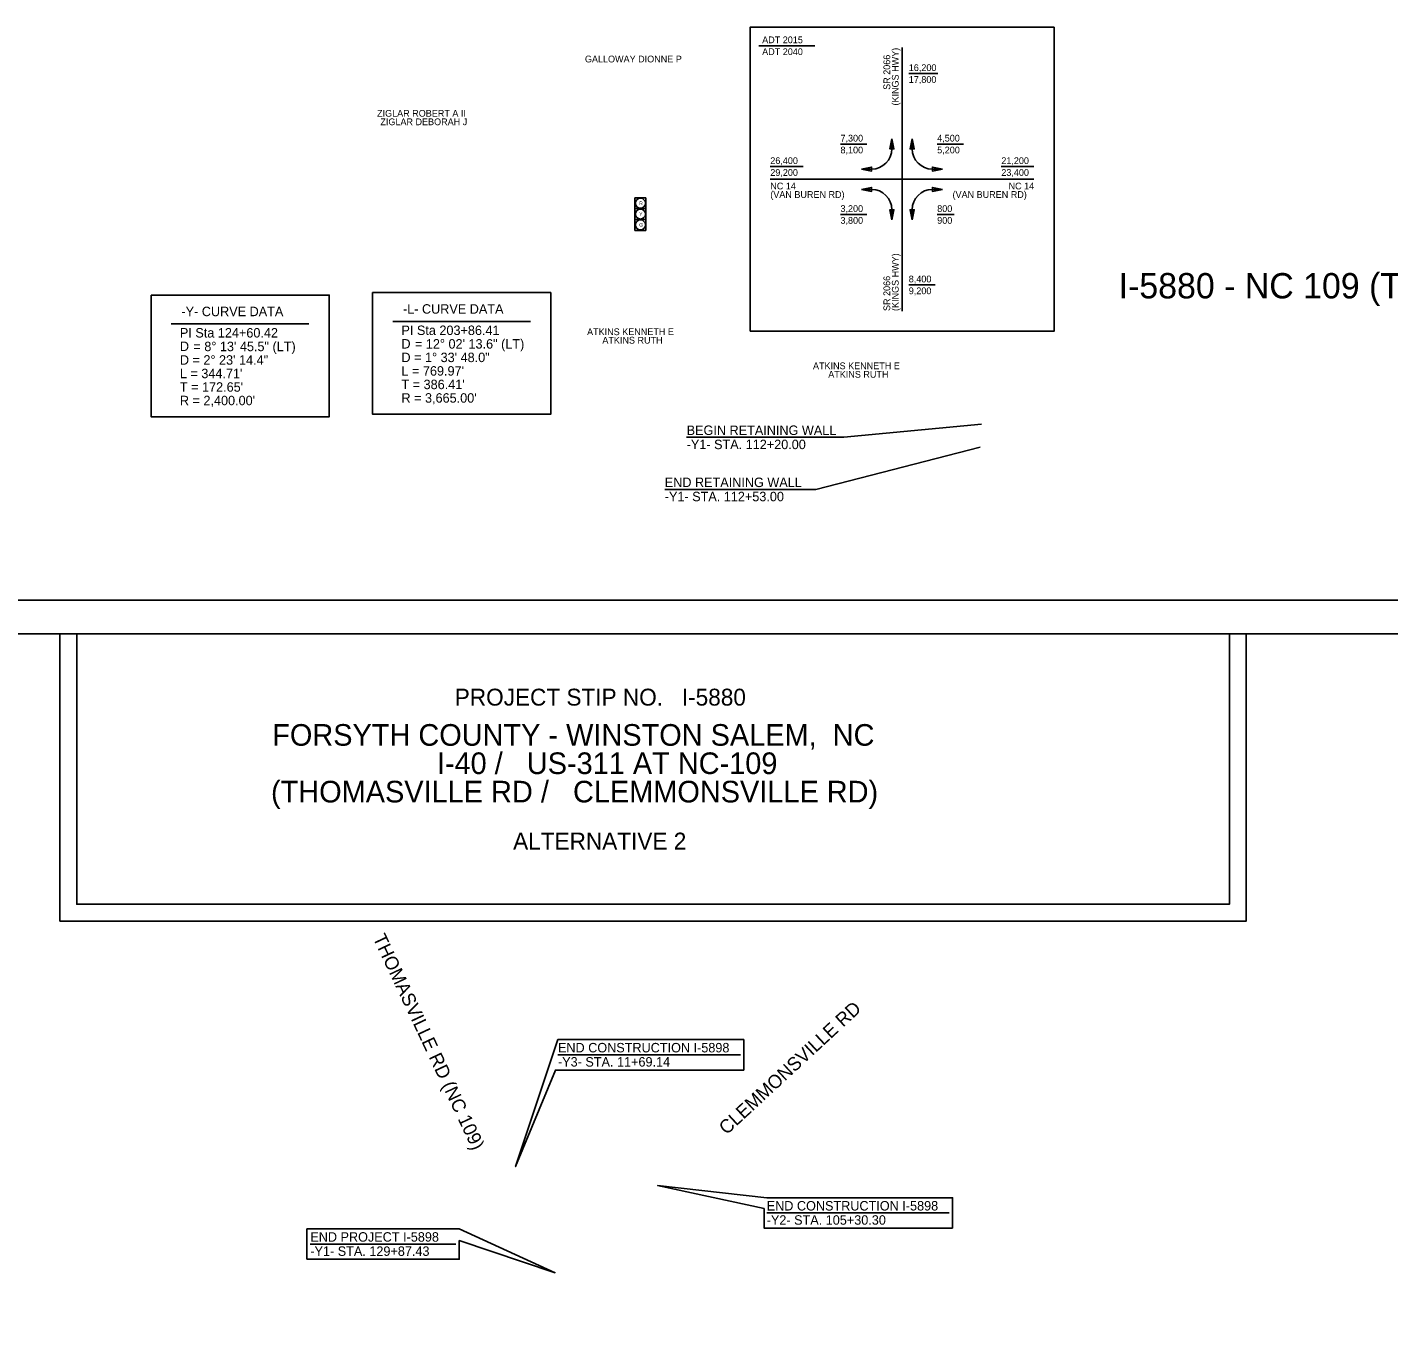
# Model space of a CAD drawing. Extents: x 1636954 to 1644154, y 841334 to 845582.
# Drawn here: x 1639588 to 1641603, y 843634 to 845582 of the extents above; entities that cross this region are included whole.
import ezdxf

# ---------------------------------------------------------------- set-up
doc = ezdxf.new("R2010")
doc.units = 0
for name, color, linetype in [('Default', 7, 'Continuous'), ('Exist Property Line PSD Text', 7, 'Continuous'), ('Exist Roads EOT Text', 7, 'Continuous'), ('Prop CMT Concrete Wall', 7, 'Continuous'), ('Prop Conc 2ft 6in Curb and Gutter', 7, 'Continuous'), ('Prop Horizontal Alignment Curve and Spiral Data', 7, 'Continuous'), ('Prop PHM Label Text', 7, 'Continuous'), ('Prop PHM Legend CELL', 7, 'Continuous'), ('Scratch_Level_0', 7, 'Continuous'), ('Scratch_Level_1', 7, 'Continuous'), ('Sheet Plan And Profile CELL', 7, 'Continuous'), ('Sheet Title CELL', 7, 'Continuous')]:
    doc.layers.add(name, color=color, linetype=linetype)

msp = doc.modelspace()

# ---------------------------------------------------------------- linework, layer by layer
at = {"layer": 'Prop CMT Concrete Wall'}
for points in [[(1640487.3, 845329.3), (1640487.3, 845313.3), (1640503.3, 845313.3), (1640503.3, 845329.3)], [(1640487.3, 845313.3), (1640487.3, 845297.2), (1640503.3, 845297.2), (1640503.3, 845313.3)], [(1640487.3, 845297.2), (1640487.3, 845281.2), (1640503.3, 845281.2), (1640503.3, 845297.2)]]:
    msp.add_lwpolyline(points, close=True, dxfattribs=at)
for centre in [(1640495.4, 845321.3), (1640495.4, 845305.3), (1640495.4, 845289.3)]:
    msp.add_circle(centre, 7.37, dxfattribs=at)
at = {"layer": 'Prop Conc 2ft 6in Curb and Gutter'}
for p, q in [((1641000.5, 844994.5), (1640796.5, 844974.9)), ((1640796.5, 844974.9), (1640563.8, 844974.9)), ((1640998.4, 844960.2), (1640754.8, 844897.8)), ((1640754.8, 844897.8), (1640531.4, 844897.8)), ((1640373.3, 844061.2), (1640643.4, 844061.2)), ((1640682.3, 843827.2), (1640952.4, 843827.2)), ((1640006.7, 843781.1), (1640222.2, 843781.1))]:
    msp.add_line(p, q, dxfattribs=at)
for points in [[(1640648.4, 844038.6), (1640648.4, 844083.7), (1640373.3, 844083.7), (1640310.6, 843895.7), (1640369.5, 844038.6), (1640369.5, 844038.6)], [(1640957.4, 843804.6), (1640957.4, 843849.7), (1640682.3, 843849.7), (1640520.7, 843867.5), (1640678.5, 843833.5), (1640678.5, 843804.6)], [(1640001.7, 843758.5), (1640001.7, 843803.6), (1640227.2, 843803.6), (1640369, 843738.6), (1640227.2, 843786.1), (1640227.2, 843758.5)]]:
    msp.add_lwpolyline(points, close=True, dxfattribs=at)
at = {"layer": 'Prop Horizontal Alignment Curve and Spiral Data'}
for points in [[(1639770.9, 845185.4), (1639770.9, 845005.4), (1640034.6, 845005.4), (1640034.6, 845185.4)], [(1640098.9, 845189.1), (1640098.9, 845009.1), (1640362.6, 845009.1), (1640362.6, 845189.1)]]:
    msp.add_lwpolyline(points, close=True, dxfattribs=at)
at = {"layer": 'Prop PHM Legend CELL'}
for p, q in [((1640670.6, 845554.3), (1640753.6, 845554.3)), ((1640882.6, 845551.8), (1640882.6, 845161.8)), ((1640892.6, 845513.1), (1640935.4, 845513.1)), ((1640791.5, 845408.8), (1640830.5, 845408.8)), ((1640867.6, 845401.8), (1640867.6, 845416.8)), ((1640897.6, 845401.8), (1640897.6, 845416.8)), ((1640934.7, 845408.8), (1640973.7, 845408.8)), ((1640687.6, 845375.5), (1640736.1, 845375.5)), ((1640837.6, 845371.8), (1640822.6, 845371.8)), ((1640927.6, 845371.8), (1640942.6, 845371.8)), ((1641029.6, 845375.5), (1641077.6, 845375.5)), ((1640687.6, 845356.8), (1641077.6, 845356.8)), ((1640837.6, 845341.8), (1640822.6, 845341.8)), ((1640927.6, 845341.8), (1640942.6, 845341.8)), ((1640830.5, 845304.7), (1640791.5, 845304.7)), ((1640867.6, 845311.8), (1640867.6, 845296.8)), ((1640897.6, 845311.8), (1640897.6, 845296.8)), ((1640959.9, 845304.7), (1640934.7, 845304.7)), ((1640931.6, 845200.4), (1640892.6, 845200.4))]:
    msp.add_line(p, q, dxfattribs=at)
for points in [[(1640657.6, 845131.8), (1640657.6, 845581.8), (1641107.6, 845581.8), (1641107.6, 845131.8)], [(1640867.6, 845416.8), (1640870.6, 845401.8), (1640864.6, 845401.8)], [(1640897.6, 845416.8), (1640894.6, 845401.8), (1640900.6, 845401.8)], [(1640822.6, 845371.8), (1640837.6, 845374.8), (1640837.6, 845368.8)], [(1640942.6, 845371.8), (1640927.6, 845374.8), (1640927.6, 845368.8)], [(1640822.6, 845341.8), (1640837.6, 845338.8), (1640837.6, 845344.8)], [(1640942.6, 845341.8), (1640927.6, 845338.8), (1640927.6, 845344.8)], [(1640867.6, 845296.8), (1640870.6, 845311.8), (1640864.6, 845311.8)], [(1640897.6, 845296.8), (1640894.6, 845311.8), (1640900.6, 845311.8)]]:
    msp.add_lwpolyline(points, close=True, dxfattribs=at)
for centre, start, end in [((1640837.6, 845401.8), 270, 0), ((1640927.6, 845401.8), 180, 270), ((1640837.6, 845311.8), 0, 90), ((1640927.6, 845311.8), 90, 180)]:
    msp.add_arc(centre, 30, start, end, dxfattribs=at)
at = {"layer": 'Scratch_Level_0'}
for p, q in [((1639800.9, 845142.7), (1640004.6, 845142.7)), ((1640128.9, 845146.4), (1640332.6, 845146.4))]:
    msp.add_line(p, q, dxfattribs=at)
at = {"layer": 'Scratch_Level_1'}
msp.add_lwpolyline([(1636954.2, 841333.9), (1636954.2, 844733.9), (1644154.2, 844733.9), (1644154.2, 841333.9)], close=True, dxfattribs=at)
msp.add_lwpolyline([(1641392.3, 844683.9), (1641392.3, 844258.9), (1639635.9, 844258.9), (1639635.9, 844683.9)], dxfattribs=at)
at = {"layer": 'Sheet Plan And Profile CELL'}
for points in [[(1637004.2, 841383.9), (1637004.2, 844683.9), (1644104.2, 844683.9), (1644104.2, 841383.9)], [(1639660.9, 844683.9), (1641367.3, 844683.9), (1641367.3, 844283.9), (1639660.9, 844283.9)]]:
    msp.add_lwpolyline(points, close=True, dxfattribs=at)

# ---------------------------------------------------------------- texts
at = {"layer": 'Default'}
for s, height, p in [('PROJECT STIP NO.   I-5880', 25, (1640220.5, 844577.9)), ('FORSYTH COUNTY - WINSTON SALEM,  NC', 32, (1639950.3, 844518.5)), ('I-40 /   US-311 AT NC-109', 32, (1640194, 844476.6)), ('(THOMASVILLE RD /   CLEMMONSVILLE RD)', 32, (1639948.5, 844434.6)), ('ALTERNATIVE 2', 25, (1640306.9, 844364.9))]:
    msp.add_text(s, height=height, rotation=360, dxfattribs=at).set_placement(p)
at = {"layer": 'Exist Property Line PSD Text'}
for s, p in [('GALLOWAY DIONNE P', (1640413.2, 845529.7)), ('ATKINS KENNETH E', (1640416.4, 845126.1)), ('ATKINS RUTH', (1640439, 845113.6)), ('ATKINS KENNETH E', (1640750.8, 845075.7)), ('ATKINS RUTH', (1640773.4, 845063.1))]:
    msp.add_text(s, height=10, dxfattribs=at).set_placement(p)
for s, p in [('ZIGLAR ROBERT A II', (1640105.5, 845449.4)), ('ZIGLAR DEBORAH J', (1640110.4, 845436.8))]:
    msp.add_text(s, height=10, rotation=360, dxfattribs=at).set_placement(p)
at = {"layer": 'Exist Roads EOT Text'}
for s, rotation, p in [('THOMASVILLE RD (NC 109)', 295.1635, (1640098.8, 844234.3)), ('CLEMMONSVILLE RD', 42.7382, (1640622.9, 843941.8))]:
    msp.add_text(s, height=20, rotation=rotation, dxfattribs=at).set_placement(p)
at = {"layer": 'Prop CMT Concrete Wall'}
for s, p in [('R', (1640493.5, 845318.6)), ('Y', (1640493.5, 845302.6)), ('G', (1640493.5, 845286.7))]:
    msp.add_text(s, height=5.34, rotation=360, dxfattribs=at).set_placement(p)
at = {"layer": 'Prop Conc 2ft 6in Curb and Gutter'}
for s, p in [('BEGIN RETAINING WALL', (1640563.8, 844978.4)), ('-Y1- STA. 112+20.00', (1640563.8, 844957.4)), ('END RETAINING WALL', (1640531.4, 844901.3)), ('-Y1- STA. 112+53.00', (1640531.4, 844880.3))]:
    msp.add_text(s, height=14, dxfattribs=at).set_placement(p)
for s, p in [('END CONSTRUCTION I-5898', (1640373.3, 844064.7)), ('-Y3- STA. 11+69.14', (1640373.3, 844043.7)), ('END CONSTRUCTION I-5898', (1640682.3, 843830.7)), ('-Y2- STA. 105+30.30', (1640682.3, 843809.7)), ('END PROJECT I-5898', (1640006.7, 843784.6)), ('-Y1- STA. 129+87.43', (1640006.7, 843763.6))]:
    msp.add_text(s, height=14, rotation=360, dxfattribs=at).set_placement(p)
at = {"layer": 'Prop Horizontal Alignment Curve and Spiral Data'}
for s, p in [('-Y- CURVE DATA', (1639815.9, 845154.2)), ('-L- CURVE DATA', (1640143.9, 845157.9))]:
    msp.add_text(s, height=14, dxfattribs=at).set_placement(p)
for s, p in [('PI Sta 203+86.41', (1640141.6, 845126.3)), ('PI Sta 124+60.42', (1639813.6, 845122.6)), ('D ', (1640141.6, 845106.3)), ('= 12%%d 02\' 13.6" (LT)', (1640161.6, 845106.2)), ('D ', (1639813.6, 845102.6)), ('= 8%%d 13\' 45.5" (LT)', (1639833.6, 845102.4)), ('D = 1%%d 33\' 48.0"', (1640141.6, 845086.2)), ('D = 2%%d 23\' 14.4"', (1639813.6, 845082.4)), ("L = 769.97'", (1640141.6, 845066.2)), ("L = 344.71'", (1639813.6, 845062.4)), ("T = 386.41'", (1640141.6, 845046.2)), ("T = 172.65'", (1639813.6, 845042.4)), ("R = 3,665.00'", (1640141.6, 845026.2)), ("R = 2,400.00'", (1639813.6, 845022.4))]:
    msp.add_text(s, height=14, rotation=360, dxfattribs=at).set_placement(p)
at = {"layer": 'Prop PHM Label Text'}
for s, p in [('ADT 2015', (1640675.6, 845558.1)), ('ADT 2040', (1640675.6, 845540.6)), ('16,200', (1640892.6, 845516.9)), ('17,800', (1640892.6, 845499.4)), ('7,300', (1640791.5, 845412.6)), ('4,500', (1640934.7, 845412.6)), ('8,100', (1640791.5, 845395.1)), ('5,200', (1640934.7, 845395.1)), ('26,400', (1640687.6, 845379.3)), ('21,200', (1641029.6, 845379.3)), ('29,200', (1640687.6, 845361.8)), ('23,400', (1641029.6, 845361.8)), ('(VAN BUREN RD)', (1640687.6, 845329.2)), ('NC 14', (1640687.6, 845341.8)), ('3,200', (1640791.5, 845308.4)), ('3,800', (1640791.5, 845290.9)), ('800', (1640934.7, 845308.4)), ('900', (1640934.7, 845290.9))]:
    msp.add_text(s, height=10, dxfattribs=at).set_placement(p)
for s, rotation, p in [('(KINGS HWY)', 90, (1640877.6, 845465.9)), ('SR 2066', 90, (1640865.1, 845489.1)), ('(VAN BUREN RD)', 360, (1640957.4, 845329.2)), ('NC 14', 360, (1641040.3, 845341.8)), ('(KINGS HWY)', 90, (1640877.6, 845161.8)), ('SR 2066', 90, (1640865.1, 845161.8)), ('8,400', 360, (1640892.6, 845204.2)), ('9,200', 360, (1640892.6, 845186.7))]:
    msp.add_text(s, height=10, rotation=rotation, dxfattribs=at).set_placement(p)
at = {"layer": 'Sheet Title CELL'}
msp.add_text('I-5880 - NC 109 (THOMASVILLE RD) FROM CHARLES ST', height=37.5, rotation=360, dxfattribs=at).set_placement((1641203.3, 845180.5))

doc.saveas('drawing.dxf')
